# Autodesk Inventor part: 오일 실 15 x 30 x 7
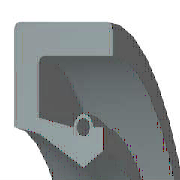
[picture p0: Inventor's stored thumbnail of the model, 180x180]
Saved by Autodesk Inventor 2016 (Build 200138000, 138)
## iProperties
Created: 2012-02
Part Number: 오일 실 15 x 30 x 7
Material: 고무
Description: 오일-실
Document SubType Name: Modeling
Standard: KS B 2804
Designer: mduedu
Standards Organization: KS
Language: ko-KR
Size Designation: S - 15 25 7
Categories: <MemberInstance><Categories><Category DisplayName="샤프트 부품" InternalName="7f7aeb1f-a693-4053-b835-cee3144e0d98" Mnemonic="SHFT"><Category DisplayName="실링" Intern
Density: 0.93 g/cm^3
Appearance: 고무 - 검은색 - 버전 1.1
IsCustomPart: 1
Author: mduedu
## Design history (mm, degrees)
revolve "본체" stored, may be unused: angle "d17" = 90 deg
revolve "스프링1" stored, may be unused: angle "d18" = 90 deg
body "Solid1"
sketch "스케치1"
  geometry: L1 (0, 15)-(7, 15); L2 (7, 15)-(7, 13.75); L3 (7, 13.75)-(1.75, 13.75); L4 (0, 15)-(0, 9.6); L5 (0, 9.6)-(1.75, 9.25); L6 (1.75, 9.25)-(4.9, 7.5); L7 (4.9, 7.5)-(0, 7.5); L8 (6.3, 8.375)-(6.3, 9.6); L9 (0, 0)-(9.586, 0) reference; L10 (4.9, 7.5)-(6.3, 8.375); L11 (0, 15)-(0, -2.5) reference; L12 (-1.917, 0)-(11.503, 0) reference; L13 (4.2, 9.6)-(1.75, 10.09); L14 (1.75, 10.09)-(1.75, 13.75); L15 (6.3, 9.6)-(5.6, 9.6); C1 r 0.455 at (4.9, 9.6); A1 r 0.7 centre (4.9, 9.6) between (5.6, 9.6) and (4.2, 9.6)
  constraints: 26 end point, 5 horizontal alignment, 4 perpendicular, 2 centre point, 2 collinear, 2 horizontal, 2 parallel, 2 point on circle, 2 point on line, 2 vertical alignment, 1 coincident
  dimensions: "d0" = 30 diameter of L1 L9 (= SD2); "d1" = 16.75 diameter of L8.start L9 (= ABDM); "d2" = 1.25 distance of L1.end L2.end (computed from SD); "d3" = 0.91 diameter of C1 (= SPDI); "d4" = 1.4 diameter of A1 (= SPDA); "d5" = 15 diameter of L6.end L9 (= NND); "d6" = 18.5 diameter of L5.end L9 (= TKDM); "d7" = 19.2 diameter of L4.end L9 (= HLDM); "d8" = 4.9 distance from line of C1.centre L4 (= SPDST); "d9" = 6.3 distance between parallel lines of L8 L4 (= SDI); "d10" = 7 distance between parallel lines of L2 L4 (= SWDT); "d12" = 1.75 distance between parallel lines of L14 L4 (= SD)
fillet "모깎기1" dims "d11" = 0.5 (= RR)
other parameters: "SD2" = 30 [user parameter; used in 1 equation term], "SWDT" = 7 [user parameter; used in 1 equation term], "RR" = 0.5 [user parameter; used in 1 equation term], "SD" = 1.75 [user parameter; used in 2 equation terms], "NND" = 15 [user parameter; used in 1 equation term], "SPDA" = 1.4 [user parameter; used in 1 equation term], "SPDI" = 0.91 [user parameter; used in 1 equation term], "TKDM" = 18.5 [user parameter; used in 1 equation term], "HLDM" = 19.2 [user parameter; used in 1 equation term], "ABDM" = 16.75 [user parameter; used in 1 equation term], "SDI" = 6.3 [user parameter; used in 1 equation term], "SPDST" = 4.9 [user parameter; used in 1 equation term], "d13" = 0, "d14" = 0, "d15" = 0, "LAB" = 0.35 [user parameter]
